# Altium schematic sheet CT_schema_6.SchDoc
size 382 x 218 mm
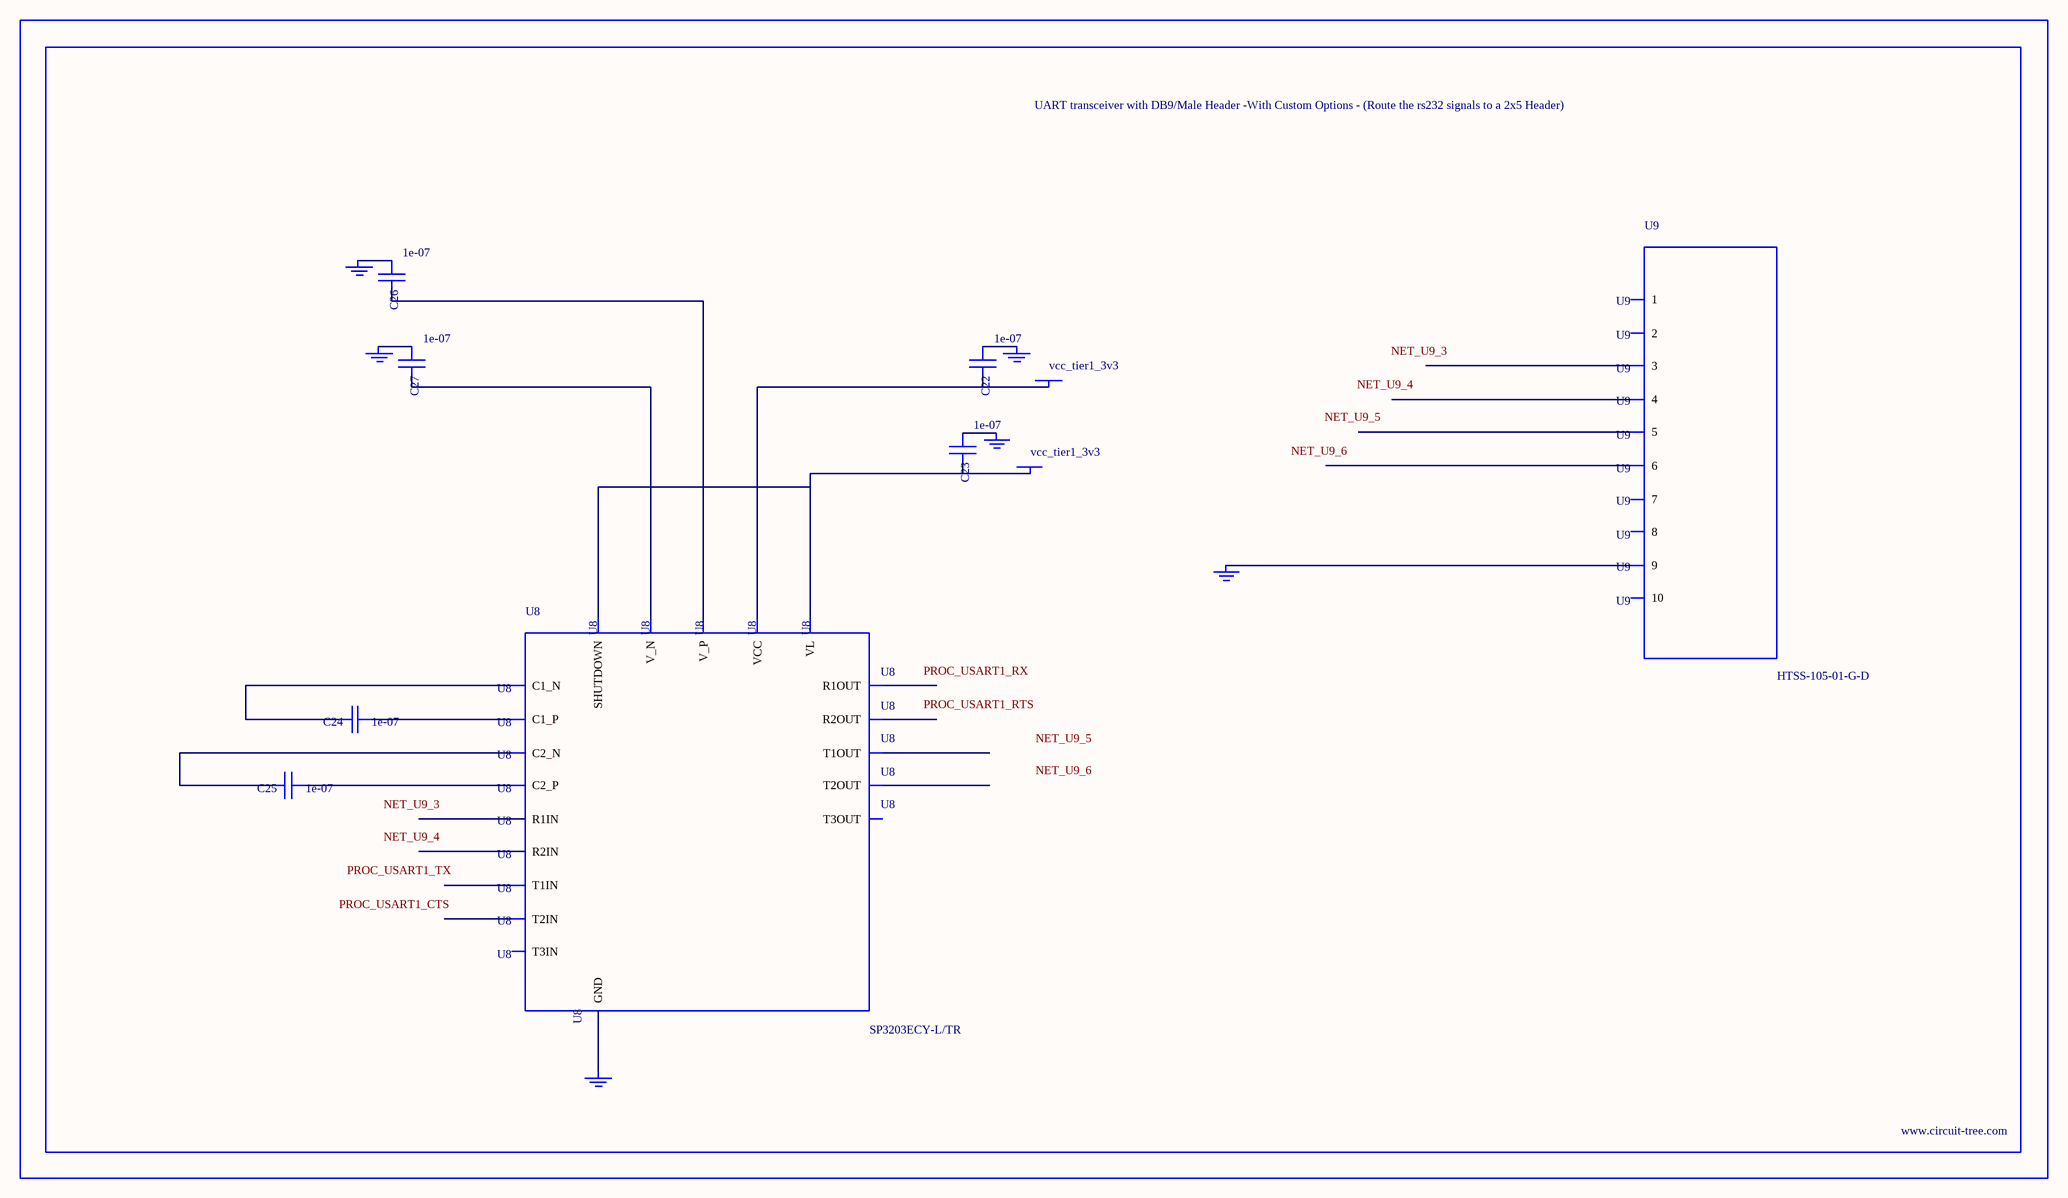
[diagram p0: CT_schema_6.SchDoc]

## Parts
BORDER5  (no value)
C22  1e-07  [C0402]
C23  1e-07  [C0402]
C24  1e-07  [C0402]
C25  1e-07  [C0402]
C26  1e-07  [C0402]
C27  1e-07  [C0402]
GND_INSTANCE_5_0  (no value)
GND_INSTANCE_5_1  (no value)
GND_INSTANCE_5_2  (no value)
GND_INSTANCE_5_3  (no value)
GND_INSTANCE_5_4  (no value)
GND_INSTANCE_5_5  (no value)
POWER_INSTANCE_5_0  vcc_tier1_3v3
POWER_INSTANCE_5_1  vcc_tier1_3v3
U8  SP3203ECY-L/TR  [TSSOP20-I]
U9  HTSS-105-01-G-D  [HTSS-105-01-G-D]

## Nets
NetC22_1: C22.1 GND_INSTANCE_5_3.0(GND)
NetC22_2: C22.2 POWER_INSTANCE_5_1.0(PWR) U8.19(VCC)
NetC23_1: C23.1 GND_INSTANCE_5_2.0(GND)
NetC23_2: C23.2 POWER_INSTANCE_5_0.0(PWR) U8.12(VL) U8.20(SHUTDOWN)
NetC24_1: C24.1 U8.1(C1_P)
NetC24_2: C24.2 U8.3(C1_N)
NetC25_1: C25.1 U8.4(C2_P)
NetC25_2: C25.2 U8.5(C2_N)
NetC26_1: C26.1 GND_INSTANCE_5_0.0(GND)
NetC26_2: C26.2 U8.2(V_P)
NetC27_1: C27.1 GND_INSTANCE_5_1.0(GND)
NetC27_2: C27.2 U8.6(V_N)
NetGND_INSTANCE_5_4_0: GND_INSTANCE_5_4.0(GND) U8.18(GND)
NetGND_INSTANCE_5_5_0: GND_INSTANCE_5_5.0(GND) U9.9

Not connected (* = marked no-connect by the designer): U8 7(T1IN) 8(T2IN) 9(T3IN) 10(R2OUT) 11(R1OUT) 13(R2IN) 14(R1IN) 15(T3OUT) 16(T2OUT) 17(T1OUT); U9 1 2 3 4 5 6 7 8 10

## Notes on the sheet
- Labels drawn without touching a wire or pin: NET_U9_3, NET_U9_4, NET_U9_5, NET_U9_6, PROC_USART1_CTS, PROC_USART1_RTS, PROC_USART1_RX, PROC_USART1_TX

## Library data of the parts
BORDER5 = BORDER_PAGE5
C22-C27 = C0402C104K3RACTU
GND_INSTANCE_5_0-GND_INSTANCE_5_5 = GND
POWER_INSTANCE_5_0 POWER_INSTANCE_5_1 = PWR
